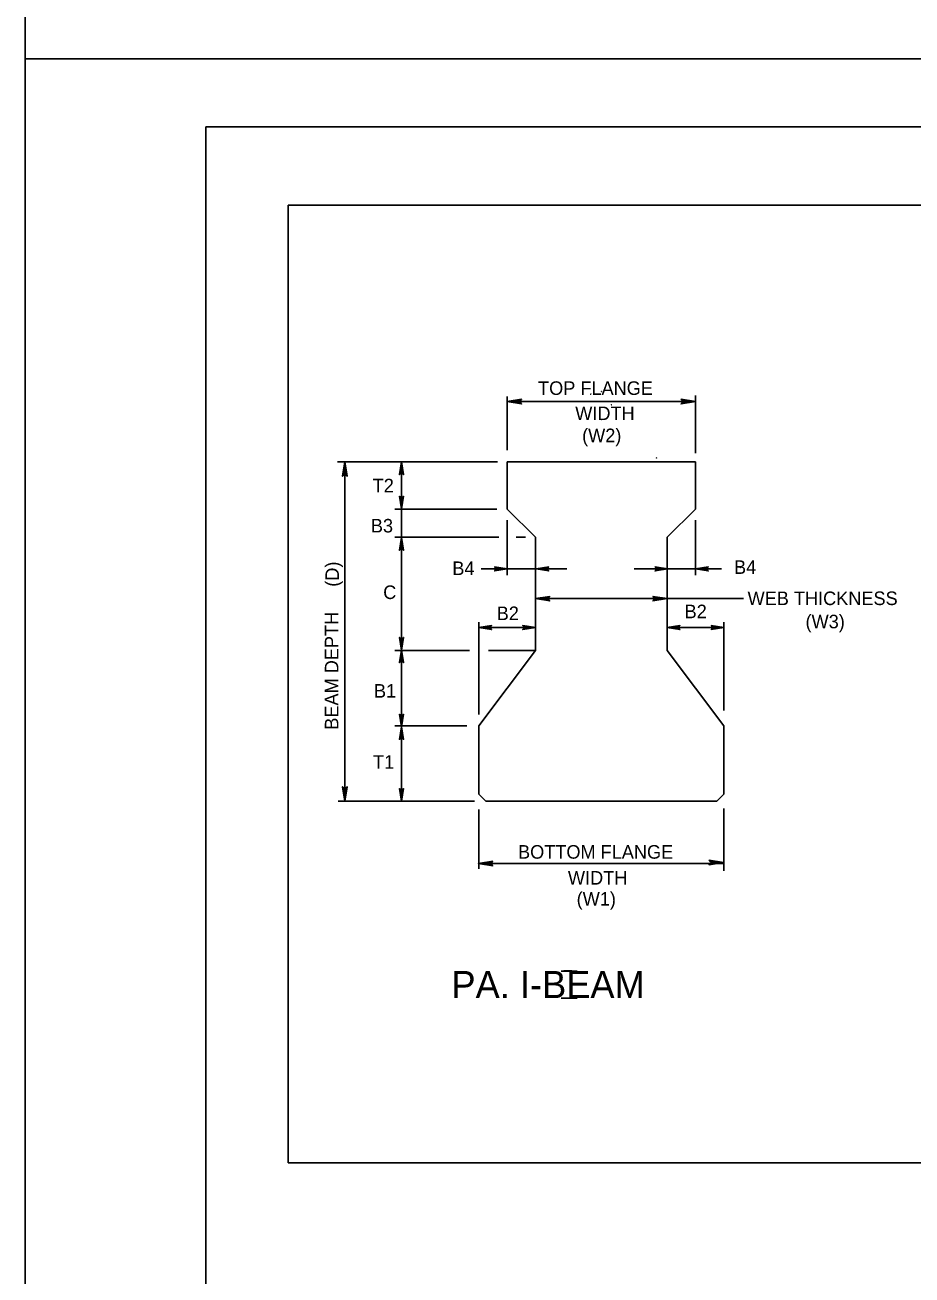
# Model space of a CAD drawing. Extents: x 635698 to 639877, y 296617 to 300175.
# Drawn here: x 638802.3 to 638998.6, y 299176.7 to 299453.3 of the extents above; entities that cross this region are included whole.
import ezdxf

# ---------------------------------------------------------------- set-up
doc = ezdxf.new("R2010")
doc.units = 0
for name, color, linetype in [('1', 7, 'Continuous'), ('2', 7, 'Continuous'), ('3', 7, 'Continuous'), ('4', 7, 'Continuous'), ('PLT-BNDY', 7, 'Continuous')]:
    doc.layers.add(name, color=color, linetype=linetype)

msp = doc.modelspace()

# ---------------------------------------------------------------- linework, layer by layer
at = {"layer": '1'}
for p, q in [((639412.37, 299413.41), (638860.56, 299413.41)), ((638860.56, 299413.41), (638860.56, 299201.54)), ((639412.37, 299201.54), (638860.56, 299201.54))]:
    msp.add_line(p, q, dxfattribs=at)
at = {"layer": '2'}
for p, q in [((638842.3, 298866.8), (638842.3, 299430.8)), ((638842.3, 299430.8), (639628.3, 299430.8)), ((638909.01, 299371.12), (638909.01, 299359.23)), ((638950.71, 299371.33), (638950.71, 299358.59)), ((638950.71, 299369.99), (638909.01, 299369.99)), ((638906.91, 299356.63), (638871.43, 299356.63)), ((638873.08, 299356.63), (638873.08, 299281.58)), ((638885.63, 299356.63), (638885.63, 299346.27)), ((638909.01, 299346.21), (638909.01, 299356.63)), ((638950.71, 299356.63), (638909.01, 299356.63)), ((638950.71, 299346.21), (638950.71, 299356.63)), ((638906.7, 299346.21), (638884.16, 299346.21)), ((638885.63, 299346.27), (638885.63, 299339.88)), ((638909.01, 299343.72), (638909.01, 299331.6)), ((638950.71, 299343.72), (638950.71, 299331.6)), ((638907.15, 299339.96), (638884.16, 299339.96)), ((638885.63, 299339.88), (638885.63, 299315.02)), ((638913.07, 299339.96), (638910.99, 299339.96)), ((638915.27, 299314.94), (638915.27, 299339.96)), ((638944.45, 299314.94), (638944.45, 299339.96)), ((638909.01, 299332.95), (638903.28, 299332.95)), ((638915.41, 299332.95), (638909.01, 299332.95)), ((638922.21, 299332.95), (638915.41, 299332.95)), ((638944.53, 299332.95), (638937.09, 299332.95)), ((638950.71, 299332.95), (638944.53, 299332.95)), ((638956.44, 299332.95), (638950.71, 299332.95)), ((638944.45, 299326.38), (638915.27, 299326.38)), ((638961.29, 299326.38), (638944.45, 299326.38)), ((638902.76, 299321.18), (638902.76, 299300.78)), ((638956.96, 299321.18), (638956.96, 299301.62)), ((638915.27, 299319.99), (638902.76, 299319.99)), ((638956.96, 299319.99), (638944.45, 299319.99)), ((638900.7, 299314.94), (638884.16, 299314.94)), ((638885.63, 299315.02), (638885.63, 299298.02)), ((638915.27, 299314.94), (638904.87, 299314.94)), ((638900.11, 299298.26), (638884.16, 299298.26)), ((638885.63, 299298.02), (638885.63, 299281.58)), ((638902.76, 299283.14), (638902.76, 299298.26)), ((638956.96, 299283.14), (638956.96, 299298.26)), ((638902.76, 299283.14), (638904.32, 299281.58)), ((638956.96, 299283.14), (638955.4, 299281.58)), ((638901.81, 299281.58), (638871.63, 299281.58)), ((638902.76, 299279.74), (638902.76, 299266.57)), ((638955.4, 299281.58), (638904.32, 299281.58)), ((638956.96, 299279.94), (638956.96, 299266.14)), ((638956.96, 299267.77), (638902.66, 299267.77)), ((638921.54, 299244), (638923.29, 299244)), ((638921.54, 299238), (638923.29, 299238))]:
    msp.add_line(p, q, dxfattribs=at)
for points in [[(638927.51, 299371.64), (638927.52, 299371.64), (638927.55, 299371.66), (638927.51, 299371.64), (638927.51, 299371.64), (638927.55, 299371.66), (638927.52, 299371.63), (638927.52, 299371.63), (638927.55, 299371.66), (638927.52, 299371.62), (638927.52, 299371.63)], [(638929.85, 299372.23), (638929.86, 299372.23), (638929.86, 299372.27), (638929.85, 299372.23), (638929.85, 299372.22), (638929.86, 299372.27), (638929.86, 299372.23), (638929.87, 299372.23), (638929.86, 299372.27), (638929.87, 299372.22), (638929.87, 299372.23)], [(638932.08, 299369.26), (638932.08, 299369.27), (638932.04, 299369.27), (638932.08, 299369.26), (638932.08, 299369.26), (638932.04, 299369.27), (638932.08, 299369.27), (638932.08, 299369.28), (638932.04, 299369.27), (638932.08, 299369.28), (638932.08, 299369.28)], [(638929.87, 299366.05), (638929.86, 299366.05), (638929.86, 299366.01), (638929.87, 299366.05), (638929.87, 299366.06), (638929.86, 299366.01), (638929.86, 299366.05), (638929.86, 299366.05), (638929.86, 299366.01), (638929.85, 299366.06), (638929.86, 299366.05)], [(638942.05, 299357.5), (638942.05, 299357.51), (638942.01, 299357.51), (638942.05, 299357.5), (638942.05, 299357.5), (638942.01, 299357.51), (638942.05, 299357.51), (638942.05, 299357.52), (638942.01, 299357.51), (638942.05, 299357.52), (638942.05, 299357.52)], [(638960.62, 299333.2), (638960.62, 299333.2), (638960.63, 299333.24), (638960.62, 299333.2), (638960.62, 299333.2), (638960.63, 299333.24), (638960.63, 299333.2), (638960.63, 299333.2), (638960.63, 299333.24), (638960.63, 299333.2), (638960.63, 299333.2)]]:
    msp.add_lwpolyline(points, dxfattribs=at)
at = {"layer": '3'}
for p, q in [((638915.27, 299339.96), (638909.01, 299346.21)), ((638944.45, 299339.96), (638950.71, 299346.21)), ((638902.76, 299298.26), (638915.27, 299314.94)), ((638956.96, 299298.26), (638944.45, 299314.94))]:
    msp.add_line(p, q, dxfattribs=at)
for points in [[(638912.04, 299369.61), (638911.93, 299369.83), (638909.01, 299369.99), (638912.04, 299369.61), (638912.2, 299369.48), (638909.01, 299369.99), (638911.93, 299370.13), (638912.03, 299370.35), (638909.01, 299369.99), (638912.2, 299370.49), (638912.03, 299370.35)], [(638947.68, 299370.37), (638947.79, 299370.15), (638950.71, 299369.99), (638947.68, 299370.37), (638947.52, 299370.5), (638950.71, 299369.99), (638947.79, 299369.84), (638947.69, 299369.63), (638950.71, 299369.99), (638947.52, 299369.48), (638947.69, 299369.63)], [(638872.7, 299353.6), (638872.92, 299353.72), (638873.08, 299356.63), (638872.7, 299353.6), (638872.57, 299353.45), (638873.08, 299356.63), (638873.22, 299353.72), (638873.44, 299353.61), (638873.08, 299356.63), (638873.59, 299353.45), (638873.44, 299353.61)], [(638885.3, 299353.98), (638885.49, 299354.08), (638885.63, 299356.63), (638885.3, 299353.98), (638885.18, 299353.85), (638885.63, 299356.63), (638885.76, 299354.08), (638885.95, 299353.99), (638885.63, 299356.63), (638886.07, 299353.85), (638885.95, 299353.99)], [(638885.96, 299348.92), (638885.77, 299348.82), (638885.63, 299346.27), (638885.96, 299348.92), (638886.08, 299349.05), (638885.63, 299346.27), (638885.51, 299348.82), (638885.31, 299348.91), (638885.63, 299346.27), (638885.19, 299349.05), (638885.31, 299348.91)], [(638885.3, 299337.23), (638885.49, 299337.32), (638885.63, 299339.88), (638885.3, 299337.23), (638885.18, 299337.09), (638885.63, 299339.88), (638885.76, 299337.33), (638885.95, 299337.23), (638885.63, 299339.88), (638886.07, 299337.09), (638885.95, 299337.23)], [(638906.36, 299333.29), (638906.46, 299333.1), (638909.01, 299332.95), (638906.36, 299333.29), (638906.23, 299333.4), (638909.01, 299332.95), (638906.46, 299332.83), (638906.37, 299332.64), (638909.01, 299332.95), (638906.23, 299332.51), (638906.37, 299332.64)], [(638918.06, 299332.62), (638917.97, 299332.81), (638915.41, 299332.95), (638918.06, 299332.62), (638918.2, 299332.51), (638915.41, 299332.95), (638917.96, 299333.08), (638918.06, 299333.27), (638915.41, 299332.95), (638918.2, 299333.4), (638918.06, 299333.27)], [(638941.88, 299333.29), (638941.98, 299333.1), (638944.53, 299332.95), (638941.88, 299333.29), (638941.74, 299333.4), (638944.53, 299332.95), (638941.98, 299332.83), (638941.88, 299332.64), (638944.53, 299332.95), (638941.74, 299332.51), (638941.88, 299332.64)], [(638953.36, 299332.62), (638953.26, 299332.81), (638950.71, 299332.95), (638953.36, 299332.62), (638953.5, 299332.51), (638950.71, 299332.95), (638953.26, 299333.08), (638953.35, 299333.27), (638950.71, 299332.95), (638953.5, 299333.4), (638953.35, 299333.27)], [(638918.3, 299326), (638918.18, 299326.22), (638915.27, 299326.38), (638918.3, 299326), (638918.45, 299325.87), (638915.27, 299326.38), (638918.18, 299326.53), (638918.29, 299326.74), (638915.27, 299326.38), (638918.45, 299326.89), (638918.29, 299326.74)], [(638941.43, 299326.76), (638941.54, 299326.54), (638944.45, 299326.38), (638941.43, 299326.76), (638941.27, 299326.89), (638944.45, 299326.38), (638941.54, 299326.24), (638941.43, 299326.02), (638944.45, 299326.38), (638941.27, 299325.87), (638941.43, 299326.02)], [(638905.41, 299319.66), (638905.31, 299319.85), (638902.76, 299319.99), (638905.41, 299319.66), (638905.55, 299319.54), (638902.76, 299319.99), (638905.31, 299320.11), (638905.4, 299320.31), (638902.76, 299319.99), (638905.55, 299320.43), (638905.4, 299320.31)], [(638912.62, 299320.32), (638912.72, 299320.13), (638915.27, 299319.99), (638912.62, 299320.32), (638912.48, 299320.44), (638915.27, 299319.99), (638912.72, 299319.86), (638912.62, 299319.67), (638915.27, 299319.99), (638912.48, 299319.55), (638912.62, 299319.67)], [(638947.1, 299319.66), (638947.01, 299319.85), (638944.45, 299319.99), (638947.1, 299319.66), (638947.24, 299319.54), (638944.45, 299319.99), (638947, 299320.11), (638947.1, 299320.31), (638944.45, 299319.99), (638947.24, 299320.43), (638947.1, 299320.31)], [(638954.31, 299320.32), (638954.41, 299320.13), (638956.96, 299319.99), (638954.31, 299320.32), (638954.18, 299320.44), (638956.96, 299319.99), (638954.41, 299319.86), (638954.32, 299319.67), (638956.96, 299319.99), (638954.18, 299319.55), (638954.32, 299319.67)], [(638885.96, 299317.67), (638885.77, 299317.57), (638885.63, 299315.02), (638885.96, 299317.67), (638886.08, 299317.8), (638885.63, 299315.02), (638885.51, 299317.57), (638885.31, 299317.66), (638885.63, 299315.02), (638885.19, 299317.8), (638885.31, 299317.66)], [(638885.3, 299312.37), (638885.49, 299312.46), (638885.63, 299315.02), (638885.3, 299312.37), (638885.18, 299312.23), (638885.63, 299315.02), (638885.76, 299312.47), (638885.95, 299312.37), (638885.63, 299315.02), (638886.07, 299312.23), (638885.95, 299312.37)], [(638885.96, 299300.67), (638885.77, 299300.58), (638885.63, 299298.02), (638885.96, 299300.67), (638886.08, 299300.81), (638885.63, 299298.02), (638885.51, 299300.57), (638885.31, 299300.67), (638885.63, 299298.02), (638885.19, 299300.81), (638885.31, 299300.67)], [(638885.3, 299295.38), (638885.49, 299295.47), (638885.63, 299298.02), (638885.3, 299295.38), (638885.18, 299295.24), (638885.63, 299298.02), (638885.76, 299295.48), (638885.95, 299295.38), (638885.63, 299298.02), (638886.07, 299295.24), (638885.95, 299295.38)], [(638873.46, 299284.61), (638873.24, 299284.5), (638873.08, 299281.58), (638873.46, 299284.61), (638873.59, 299284.77), (638873.08, 299281.58), (638872.93, 299284.49), (638872.72, 299284.6), (638873.08, 299281.58), (638872.57, 299284.77), (638872.72, 299284.6)], [(638885.96, 299284.23), (638885.77, 299284.13), (638885.63, 299281.58), (638885.96, 299284.23), (638886.08, 299284.37), (638885.63, 299281.58), (638885.51, 299284.13), (638885.31, 299284.22), (638885.63, 299281.58), (638885.19, 299284.37), (638885.31, 299284.22)], [(638905.68, 299267.39), (638905.57, 299267.61), (638902.66, 299267.77), (638905.68, 299267.39), (638905.84, 299267.26), (638902.66, 299267.77), (638905.57, 299267.92), (638905.68, 299268.13), (638902.66, 299267.77), (638905.84, 299268.28), (638905.68, 299268.13)], [(638953.87, 299268.38), (638953.99, 299268.16), (638956.9, 299268), (638953.87, 299268.38), (638953.72, 299268.51), (638956.9, 299268), (638953.99, 299267.85), (638953.88, 299267.64), (638956.9, 299268), (638953.72, 299267.49), (638953.88, 299267.64)]]:
    msp.add_lwpolyline(points, dxfattribs=at)
at = {"layer": '4'}
for p, q in [((638924.51, 299243.99), (638920.96, 299243.99)), ((638924.51, 299238.02), (638920.96, 299238.02))]:
    msp.add_line(p, q, dxfattribs=at)
at = {"layer": 'PLT-BNDY'}
for points in [[(638802.3, 300039.8), (639643.3, 300039.8), (639643.3, 299445.8), (638802.3, 299445.8)], [(638802.3, 299445.8), (639643.3, 299445.8), (639643.3, 298851.8), (638802.3, 298851.8)]]:
    msp.add_lwpolyline(points, close=True, dxfattribs=at)

# ---------------------------------------------------------------- texts
at = {"layer": '1'}
msp.add_text('C', height=3, dxfattribs=at).set_placement((638881.58, 299326.3))
at = {"layer": '2'}
msp.add_text('PA. I-BEAM', height=6, dxfattribs=at).set_placement((638896.67, 299238))
at = {"layer": '3'}
for s, height, p in [('TOP FLANGE', 3.001, (638915.85, 299371.46)), ('WIDTH', 3.001, (638924.08, 299365.89)), ('(W2)', 3, (638925.6, 299361)), ('T2', 3, (638879.25, 299349.9)), ('B3', 3, (638878.85, 299341.02)), ('B4', 3, (638896.88, 299331.61)), ('B4', 3, (638959.22, 299331.86)), ('WEB THICKNESS', 3.001, (638962.22, 299324.96)), ('B2', 3, (638906.7, 299321.64)), ('B2', 3, (638948.28, 299322.05)), ('(W3)', 3, (638975.05, 299319.82)), ('B1', 3, (638879.53, 299304.48)), ('T1', 3, (638879.33, 299288.74)), ('BOTTOM FLANGE', 3.001, (638911.42, 299268.85)), ('WIDTH', 3.001, (638922.46, 299263.12)), ('(W1)', 3, (638924.39, 299258.46))]:
    msp.add_text(s, height=height, dxfattribs=at).set_placement(p)
for s, height, p in [('(D)', 3, (638871.78, 299329.02)), ('BEAM DEPTH', 3.001, (638871.65, 299297.38))]:
    msp.add_text(s, height=height, rotation=90, dxfattribs=at).set_placement(p)

doc.saveas('drawing.dxf')
